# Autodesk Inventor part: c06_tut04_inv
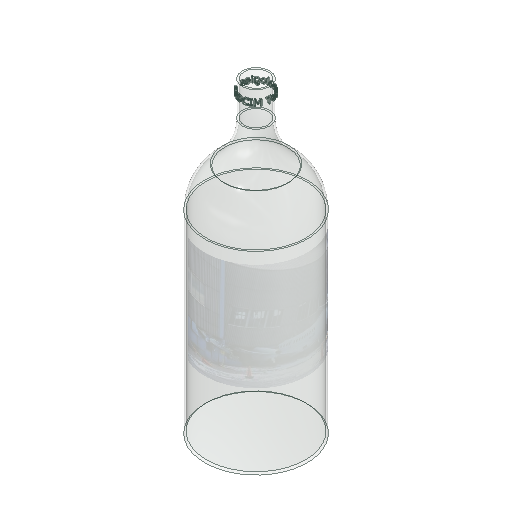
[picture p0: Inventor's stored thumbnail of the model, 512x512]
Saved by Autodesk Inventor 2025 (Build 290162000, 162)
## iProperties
Created: 2015-03
Part Number: c06_tut04_inv
Material: Glass
Document SubType Name: Modeling
Designer: Sandeep
Density: 2.18 g/cm^3
Appearance: Clear
Author: Sandeep
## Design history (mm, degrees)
sketch "Sketch1"
  geometry: L1 (8, 180)-(8, 160); L2 (30, 113.567)-(30, 0); L3 (30, 0)-(0, 0); L4 (0, 0)-(0, -98.027); L5 (7, 180)-(7, 160); L6 (29, 113.567)-(29, 1); L7 (29, 1)-(0, 1); L8 (8, 180)-(7, 180); L9 (0, 1)-(0, 0); A1 r 30 centre (38, 160) between (8, 160) and (19, 136.784); A2 r 30 centre (0, 113.567) between (30, 113.567) and (19, 136.784); A3 r 31 centre (38, 160) between (7, 160) and (18.367, 136.01); A4 r 29 centre (0, 113.567) between (29, 113.567) and (18.367, 136.01)
  constraints: 18 end point, 8 point on circle, 4 centre point, 3 perpendicular, 3 tangent, 2 parallel, 2 vertical, 1 horizontal, 4 other
  dimensions: "d0" = 20 distance of L1.start L1.end; "d1" = 30 radius of A1; "d2" = 30 radius of A2; "d7" = 180 vertical distance of L3.end L1.start; "d17" = 1 distance between parallel lines of L5 L1; "d18" = 60 diameter of L2 L4; "d19" = 16 diameter of L1 L4
revolve "Revolution1" sketch "Sketch1" stored, may be unused: angle "d9" = 90 deg
workplane "Work Plane1"
sketch "Sketch2"
  geometry: L1 (-21.117, 118.431)-(137.947, 118.431); L2 (137.947, 118.431)-(137.947, 105.984); L3 (137.947, 105.984)-(-21.117, 105.984); L4 (-21.117, 105.984)-(-21.117, 118.431); 1 further point
  constraints: 2 other
emboss "Emboss1" sketch "Sketch2" dims "d1" = 30, "d10" = 1, "d11" = 0
sketch "Sketch3"
  geometry: L1 (-60.338, 49.443)-(58.204, 49.443); L2 (58.204, 49.443)-(58.204, -13.263); L3 (58.204, -13.263)-(-60.338, -13.263); L4 (-60.338, -13.263)-(-60.338, 49.443); 1 further point; 1 other entity
  constraints: 2 other
feature "Decal1" sketch "Sketch3"
body "Solid1"
node "Image1"
